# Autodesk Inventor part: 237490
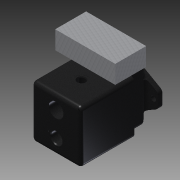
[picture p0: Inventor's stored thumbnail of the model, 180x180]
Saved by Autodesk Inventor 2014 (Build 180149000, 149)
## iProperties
Shininess: 20.0
Length Units: 11272
Angle Units: 11279
Time Units: 11290
Mass Units: 11286
Length Display Precision: 3
Angle Display Precision: 2
Company: Autodesk, Inc.
Created: 2002-07
Part Number: 237490
Material: Generic
Description: PUMP
Document SubType Name: Modeling
Designer: Autodesk, Inc.
Density: 1 g/cm^3
Mass: 8851.15 g
Surface Area: 3268.06 cm^2
Volume: 8851.15 cm^3
Appearance: Black Cast
Density: 0.0
Volumn: 0.0
Area: 0.0
PropertySet Name: Model Information
Control State: 0
Master: False
Checked Out: False
Last Check In By: JT
Last Check In Date: 2003-06-20
Title: PUMP
Author: Autodesk, Inc.
Comments: MODEL REPRESENTATION ONLY. DETAILS MAY NOT BE ACCURATE.
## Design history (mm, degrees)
sketch "Sketch1"
  geometry: L1 (-85.725, 92.075)-(85.725, 92.075); L2 (85.725, 92.075)-(85.725, -92.075); L3 (85.725, -92.075)-(-85.725, -92.075); L4 (-85.725, -92.075)-(-85.725, 92.075); 1 further point
  constraints: 8 end point, 2 parallel, 1 horizontal, 1 perpendicular
  dimensions: "d3" = 171.45 distance of L1.start L1.end; "d4" = 85.725 distance from line of L4 point (0, 0) (= 0.5 x d3); "d5" = 184.15 distance of L3.end L1.start; "d6" = 92.075 distance from line of point (0, 0) L1 (= 0.5 x d5)
extrude "Extrusion2" new body sketch "Sketch1" distance "d7" = 187.325; taper "d8" = 0 deg
sketch "Sketch2"
  geometry: L1 (85.725, 92.075)-(-85.725, 92.075) reference; L2 (-85.725, 92.075)-(-85.725, -92.075) reference; L3 (-85.725, -92.075)-(85.725, -92.075) reference; L4 (85.725, -92.075)-(85.725, 92.075) reference; L5 (-63.5, 92.075)-(63.5, 92.075); L6 (63.5, 92.075)-(63.5, -92.075); L7 (63.5, -92.075)-(-63.5, -92.075); L8 (-63.5, -92.075)-(-63.5, 92.075)
  constraints: 8 end point, 2 parallel, 2 point on line, 1 horizontal, 1 perpendicular
  dimensions: "d9" = 127 distance between parallel lines of L6 L8; "d10" = 22.225 distance between parallel lines of L2 L8; "d11" = 22.225 distance between parallel lines of L4 L6 (derived)
extrude "Extrusion3" join sketch "Sketch2" distance "d12" = 61.9125; taper "d13" = 0 deg
sketch "Sketch3"
  geometry: L1 (-106.362, 15.494)-(-106.363, -15.494); L2 (106.363, -15.494)-(106.363, 15.494); L3 (-98.279, 29.325)-(-36.216, 64.288); L4 (-98.279, -29.325)-(-36.216, -64.288); L5 (98.279, -29.325)-(36.216, -64.288); L6 (98.279, 29.325)-(36.216, 64.288); C1 r 8.731 at (90.487, 0); C2 r 8.731 at (-90.487, 0); A1 r 15.875 centre (-90.487, 15.494) between (-98.279, 29.325) and (-106.362, 15.494); A2 r 15.875 centre (-90.487, -15.494) between (-106.363, -15.494) and (-98.279, -29.325); A3 r 15.875 centre (90.487, 15.494) between (106.363, 15.494) and (98.279, 29.325); A4 r 15.875 centre (90.488, -15.494) between (98.279, -29.325) and (106.363, -15.494); A5 r 73.787 centre (0, 0) between (-36.216, -64.288) and (36.216, -64.288); A6 r 73.787 centre (0, 0) between (36.216, 64.288) and (-36.216, 64.288); 5 further points
  constraints: 12 end point, 12 point on circle, 12 tangent, 8 centre point, 8 point on line, 4 equal radius, 4 horizontal alignment, 2 vertical, 2 vertical alignment, 1 coincident
  dimensions: "d19" = 15.875 radius of A1; "d20" = 30.988 distance of A2.centre A1.centre; "d21" = 15.494 vertical distance of point (0, 0) A1.centre; "d22" = 73.787 radius of A6; "d23" = 73.787 radius of A5; "d24" = 180.975 distance of C1.centre C2.centre; "d25" = 90.4875 distance of point (0, 0) C1.centre; "d26" = 17.4625 diameter of C1
extrude "Extrusion4" join sketch "Sketch3" distance "d27" = 15.875; taper "d28" = 0 deg
fillet "Fillet1" dims "d29" = 12.7
fillet "Fillet2" dims "d30" = 12.7
fillet "Fillet3" dims "d31" = 12.7
sketch "Sketch4"
  geometry: L1 (146.05, 174.625)-(146.05, 0) reference; L2 (-61.913, 119.063)-(147.637, 119.063); L3 (147.637, 119.063)-(147.637, 227.013); L4 (147.637, 227.013)-(-61.913, 227.012); L5 (-61.913, 227.012)-(-61.913, 119.063); L6 (36.809, 252.413)-(-25.254, 252.413) reference
  constraints: 8 end point, 2 parallel, 1 horizontal, 1 perpendicular
  dimensions: "d33" = 209.55 distance of L2.start L2.end; "d34" = 25.4 distance between parallel lines of L4 L6; "d35" = 107.95 distance of L2.end L3.end; "d36" = 1.5875 distance between parallel lines of L3 L1
extrude "Extrusion5" join sketch "Sketch4" distance "d37" = 63.5; taper "d38" = 0 deg
sketch "Sketch5"
  geometry: C1 r 25.4 at (0, 44.45); 5 further points
  constraints: 3 vertical alignment, 2 horizontal alignment, 1 centre point
  dimensions: "d39" = 77.7875 distance of point (-38.894, 65.888) point (38.894, 65.888); "d40" = 38.89375 horizontal distance of point (0, 0) point (38.894, 65.888); "d41" = 44.45 distance of C1.centre point (0, 0); "d42" = 50.8 diameter of C1; "d43" = 42.8752 distance of point (-38.894, 65.888) point (-38.894, 23.012); "d44" = 21.4376 vertical distance of C1.centre point (-38.894, 23.012)
extrude "Extrusion6" cut sketch "Sketch5" distance "d45" = 63.5; taper "d46" = 0 deg
sketch "Sketch6"
  geometry: L1 (92.075, 174.625)-(92.075, 55.562) reference; L2 (92.075, 119.063)-(91.567, 119.063); L3 (91.567, 119.063)-(91.567, 113.458); L4 (91.567, 113.458)-(88.265, 111.919); L5 (88.265, 111.919)-(68.555, 111.919); L6 (68.555, 111.919)-(64.586, 107.95); L7 (64.586, 107.95)-(24.623, 107.95); L8 (24.623, 107.95)-(24.623, 98.425); L9 (24.623, 98.425)-(92.075, 98.425); L10 (-79.375, 187.325)-(79.375, 187.325) reference
  constraints: 16 end point, 3 parallel, 3 perpendicular, 2 point on line
  dimensions: "d54" = 0.508 distance between parallel lines of L1 L3; "d55" = 41.275 diameter of L2.end L9; "d56" = 19.05 diameter of L7 L9; "d57" = 88.9 distance from line of L10 L9.end; "d58" = 26.9875 diameter of L5 L9; "d59" = 65 deg angle of L3 L4; "d60" = 3.302 horizontal distance of L3.end L4.end; "d61" = 23.0124 distance from line of L5.end L3; "d62" = 45 deg angle of L5 L6
revolve "Revolution1" sketch "Sketch6" stored, may be unused: angle "d63" = 90 deg
sketch "Sketch7"
  geometry: L1 (-79.375, 187.325)-(79.375, 187.325) reference; L2 (-70.104, 187.325)-(-70.104, 186.817); L3 (-70.104, 186.817)-(-63.03, 186.817); L4 (-63.03, 186.817)-(-61.912, 182.646); L5 (-61.912, 182.646)-(-61.912, 163.805); L6 (-61.912, 163.805)-(-57.15, 159.042); L7 (-57.15, 159.042)-(-57.15, 95.234); L8 (-57.15, 95.234)-(-41.275, 95.234); L9 (-41.275, 95.234)-(-41.275, 187.325); L10 (-92.075, 0)-(-92.075, 174.625) reference
  constraints: 16 end point, 3 parallel, 3 perpendicular, 2 point on line
  dimensions: "d64" = 0.508 distance between parallel lines of L1 L3; "d65" = 50.8 distance from line of L10 L9.end; "d66" = 57.658 diameter of L2 L9; "d67" = 43.5102 diameter of L3.end L9; "d68" = 15 deg angle of L5 L4; "d69" = 41.275 diameter of L5 L9; "d70" = 45 deg angle of L5 L6; "d71" = 31.75 diameter of L7 L9; "d72" = 23.0124 distance from line of L3 L5.end
revolve "Revolution2" sketch "Sketch7" stored, may be unused: angle "d73" = 90 deg
body "Solid1"
other parameters: "d18" = 157.1244
